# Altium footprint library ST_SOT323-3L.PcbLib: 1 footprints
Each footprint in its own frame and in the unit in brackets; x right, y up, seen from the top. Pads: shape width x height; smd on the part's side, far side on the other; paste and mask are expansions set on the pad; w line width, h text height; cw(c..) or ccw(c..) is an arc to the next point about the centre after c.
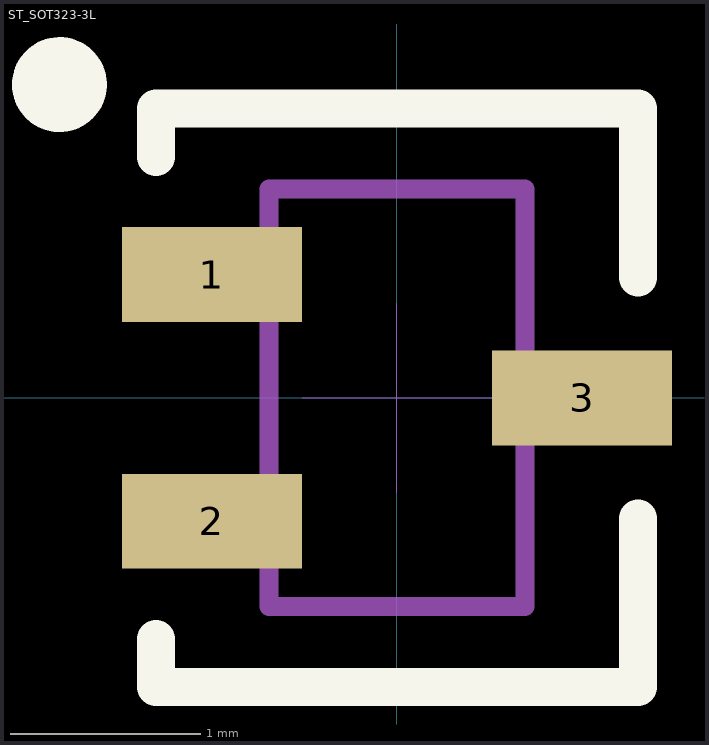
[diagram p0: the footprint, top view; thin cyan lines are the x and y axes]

## ST_SOT323-3L [mm]
height 1.1
pads (3):
  rect 0.95x0.5 smd paste-20: 1(-0.975,0.65) 2(-0.975,-0.65) 3(0.975,0)
Top Overlay:
  circle w0.25: c-1.778,1.651 r0.125
  lines w0.2: -1.27,-1.27 -1.27,-1.524 1.27,-1.524 1.27,-0.635 ; -1.27,1.27 -1.27,1.524 1.27,1.524 1.27,0.635
Top Paste:
  rectangle: 0.525,-0.235 1.425,0.235
  rectangle: -1.425,-0.885 -0.525,-0.415
  rectangle: -1.425,0.415 -0.525,0.885
Mechanical 13:
  lines w0.1: -0.675,-1.1 -0.675,1.1 0.675,1.1 0.675,-1.1 -0.675,-1.1
Mechanical 15:
  lines w0.001: -0.5,0 0.5,0 ; 0,-0.5 0,0.5
3D body "ST_SOT323.STEP": height 0.9, standoff -0.05, extent -1.076,-0.994 1.085,0.997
